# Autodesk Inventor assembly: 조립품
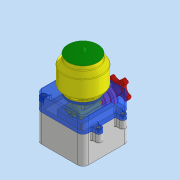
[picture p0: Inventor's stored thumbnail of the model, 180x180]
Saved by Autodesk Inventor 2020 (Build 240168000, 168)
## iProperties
Created: 2022-03
Part Number: 조립품
Document SubType Name: Assembly
Designer: Administrator
Author: Administrator
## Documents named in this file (11)
- C:\Users\Administrator\Desktop\720306V1014\조립품.iam
- C:\Users\Administrator\Desktop\720306V1014\본체.ipt
- C:\Users\Administrator\Desktop\720306V1014\본체커버.ipt
- C:\Users\Administrator\Desktop\720306V1014\핸들축.ipt
- C:\Users\Administrator\Desktop\720306V1014\앞커버.ipt
- C:\Users\Administrator\Desktop\720306V1014\베어링 부시.ipt
- C:\Users\Administrator\Desktop\720306V1014\용기.ipt
- C:\Users\Administrator\Desktop\720306V1014\용기캡.ipt
- C:\Users\Administrator\Desktop\720306V1014\핸들.ipt
- C:\Users\Administrator\Desktop\720306V1014\볼트 M3x12.ipt
- C:\Users\Administrator\Desktop\720306V1014\볼트 M4x12.ipt
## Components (2 placed, 2 different names)
1. 핸들축:1
2. 핸들:1
